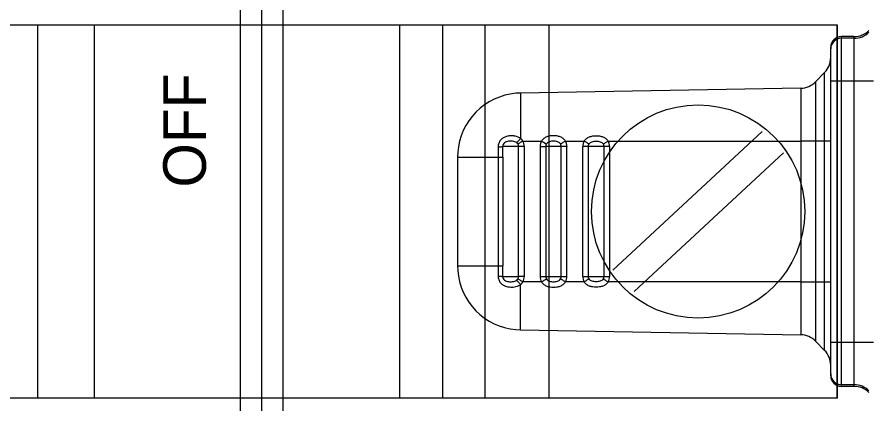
# Model space of a CAD drawing. Extents: x 0 to 4205, y 0 to 2970.
# Drawn here: x 958.55 to 998.5, y 1083.32 to 1101.46 of the extents above; entities that cross this region are included whole.
import ezdxf

# ---------------------------------------------------------------- set-up
doc = ezdxf.new("R2010")
doc.units = 0
doc.layers.add('Level 1', color=7, linetype='Continuous')

# ---------------------------------------------------------------- blocks, each defined once
blk = doc.blocks.new('NCX-2418-3U')
for p, q in [((-178, 132.85), (-178, -99.15)), ((-177, 132.85), (-177, -99.15)), ((-176, 132.85), (-176, -99.15)), ((-149.8, 17.451), (-149.8, 33.849)), ((-149.214, 33.849), (-149.8, 33.849)), ((-149.214, 33.849), (-149.8, 33.849)), ((-149.214, 33.77), (-149.8, 33.77)), ((-149.214, 33.849), (-149.214, 17.451)), ((-150.3, 17.951), (-150.3, 33.349)), ((-150.587, 32.164), (-151.013, 31.73)), ((-150.587, 19.136), (-150.587, 32.164)), ((-151.013, 31.73), (-151.013, 19.57)), ((-150.3, 31.771), (-148.3, 31.771)), ((-151.709, 31.431), (-164.852, 31.201)), ((-164.852, 31.201), (-164.852, 29.074)), ((-151.709, 31.431), (-151.709, 19.869)), ((-164.735, 28.95), (-163.865, 28.95)), ((-162.735, 28.95), (-161.865, 28.95)), ((-160.735, 28.95), (-151.709, 28.95)), ((-150.3, 28.95), (-151.709, 28.95)), ((-164.668, 28.7), (-165.674, 28.7)), ((-164.942, 22.6), (-164.942, 28.7)), ((-164.668, 22.6), (-164.668, 28.7)), ((-163.932, 28.7), (-163.932, 22.6)), ((-163.932, 28.7), (-163.664, 28.7)), ((-163.664, 28.7), (-163.664, 22.6)), ((-162.942, 28.7), (-163.664, 28.7)), ((-162.942, 22.6), (-162.942, 28.7)), ((-162.668, 28.7), (-162.942, 28.7)), ((-162.668, 22.6), (-162.668, 28.7)), ((-161.932, 22.6), (-161.932, 28.7)), ((-160.668, 28.7), (-161.932, 28.7)), ((-161.664, 22.6), (-161.664, 28.7)), ((-160.942, 28.7), (-160.942, 22.6)), ((-160.668, 28.7), (-160.668, 22.6)), ((-167.8, 28.202), (-167.8, 23.098)), ((-167.8, 28.202), (-165.67, 28.202)), ((-165.902, 28.202), (-165.902, 23.098)), ((-165.67, 28.202), (-165.67, 23.098)), ((-167.8, 23.098), (-165.902, 23.098)), ((-165.902, 23.098), (-165.67, 23.098)), ((-165.674, 22.6), (-164.942, 22.6)), ((-164.668, 22.6), (-164.942, 22.6)), ((-163.932, 22.6), (-162.668, 22.6)), ((-161.932, 22.6), (-160.668, 22.6)), ((-164.852, 20.099), (-164.852, 22.225)), ((-163.865, 22.35), (-164.735, 22.35)), ((-161.865, 22.35), (-162.735, 22.35)), ((-151.709, 22.35), (-160.735, 22.35)), ((-151.709, 22.35), (-150.3, 22.35)), ((-164.852, 20.099), (-151.709, 19.869)), ((-151.013, 19.57), (-150.587, 19.136)), ((-150.3, 19.529), (-148.3, 19.529)), ((-149.8, 17.53), (-149.214, 17.53)), ((-149.214, 17.451), (-149.8, 17.451)), ((-149.214, 17.451), (-149.8, 17.451))]:
    blk.add_line(p, q)
for points in [[(-164.852, 31.201), (-165.07, 31.19), (-165.331, 31.155), (-165.588, 31.096), (-165.84, 31.016), (-166.083, 30.914), (-166.316, 30.791), (-166.537, 30.648), (-166.746, 30.486), (-166.939, 30.306), (-167.115, 30.11), (-167.274, 29.899), (-167.413, 29.676), (-167.532, 29.44), (-167.631, 29.196), (-167.707, 28.943), (-167.761, 28.685), (-167.792, 28.423), (-167.8, 28.202)], [(-167.8, 23.098), (-167.792, 22.88), (-167.761, 22.619), (-167.708, 22.36), (-167.632, 22.108), (-167.534, 21.863), (-167.415, 21.628), (-167.276, 21.404), (-167.117, 21.193), (-166.941, 20.997), (-166.748, 20.817), (-166.541, 20.655), (-166.319, 20.511), (-166.086, 20.388), (-165.843, 20.285), (-165.592, 20.205), (-165.335, 20.146), (-165.073, 20.111), (-164.852, 20.099)]]:
    blk.add_lwpolyline(points)
for centre, radius, start, end in [((-149.214, 34.849), 1, 270, 315), ((-149.214, 34.849), 1, 269.9984, 314.9877), ((-149.214, 34.77), 1, 269.9984, 314.9877), ((-149.8, 33.349), 0.5, 90, 180), ((-149.8, 33.349), 0.5, 89.9895, 179.9895), ((-149.8, 33.27), 0.5, 89.9895, 179.9895), ((-151.3, 32.865), 1, 315.5, 359.9974), ((-151.726, 32.431), 1, 271, 315.4998), ((-165.167, 28.7), 0.499, 0.0299, 30.0713), ((-163.433, 28.7), 0.5, 149.9278, 179.963), ((-163.167, 28.7), 0.5, 0.0336, 30.0749), ((-161.433, 28.7), 0.499, 149.9288, 179.9703), ((-161.167, 28.7), 0.499, 0.0299, 30.0709), ((-194.009, 28.214), 28.339, 359.9754, 0.9825), ((-194.015, 23.086), 28.344, 359.0176, 0.0247), ((-165.167, 22.6), 0.499, 329.9312, 359.969), ((-163.433, 22.6), 0.5, 180.0364, 210.0773), ((-163.447, 22.6), 0.217, 180.0423, 211.5562), ((-163.167, 22.6), 0.499, 329.9303, 359.9687), ((-161.433, 22.6), 0.499, 180.0293, 210.0718), ((-161.167, 22.6), 0.499, 329.9282, 359.9708), ((-151.726, 18.869), 1, 44.5002, 89), ((-151.3, 18.435), 1, 0.0453, 44.5), ((-149.8, 18.03), 0.5, 180.0105, 270.0105), ((-149.8, 17.951), 0.5, 180, 270), ((-149.8, 17.951), 0.5, 180.0105, 270.0105), ((-149.214, 16.53), 1, 45.0123, 90.0016), ((-149.214, 16.451), 1, 45.0123, 90.0016), ((-149.214, 16.451), 1, 45, 90)]:
    blk.add_arc(centre, radius, start, end)
for points, degree in [([(-164.852, 29.074), (-164.897, 29.109), (-164.998, 29.163), (-165.166, 29.197), (-165.336, 29.197), (-165.504, 29.174), (-165.663, 29.109), (-165.794, 28.997), (-165.88, 28.848), (-165.901, 28.734), (-165.901, 28.678)], 3), ([(-162.735, 28.95), (-162.764, 28.995), (-162.839, 29.075), (-162.981, 29.154), (-163.139, 29.194), (-163.3, 29.204), (-163.461, 29.194), (-163.618, 29.154), (-163.761, 29.075), (-163.836, 28.995), (-163.865, 28.95)], 3), ([(-161.865, 28.95), (-161.836, 28.995), (-161.761, 29.075), (-161.619, 29.155), (-161.461, 29.194), (-161.3, 29.204), (-161.138, 29.194), (-160.981, 29.155), (-160.839, 29.075), (-160.764, 28.995), (-160.735, 28.95)], 3), ([(-165.031, 28.878), (-165.057, 28.898), (-165.119, 28.928), (-165.217, 28.942), (-165.316, 28.945), (-165.414, 28.942), (-165.511, 28.927), (-165.6, 28.881), (-165.662, 28.801), (-165.676, 28.733), (-165.674, 28.7)], 3), ([(-164.852, 29.074), (-164.887, 29.034), (-164.935, 28.978), (-164.996, 28.913), (-165.021, 28.888), (-165.031, 28.878)], 3), ([(-164.974, 28.814), (-164.989, 28.838), (-165.009, 28.86), (-165.031, 28.878)], 2), ([(-164.735, 28.95), (-164.782, 28.923), (-164.861, 28.877), (-164.941, 28.832), (-164.974, 28.814)], 3), ([(-164.942, 28.7), (-164.942, 28.72), (-164.947, 28.76), (-164.964, 28.797), (-164.974, 28.814)], 3), ([(-164.735, 28.95), (-164.766, 28.998), (-164.807, 29.04), (-164.852, 29.074)], 2), ([(-163.865, 28.95), (-163.819, 28.923), (-163.741, 28.878), (-163.663, 28.832), (-163.632, 28.814)], 3), ([(-163.632, 28.814), (-163.643, 28.797), (-163.659, 28.76), (-163.664, 28.72), (-163.664, 28.7)], 3), ([(-162.974, 28.814), (-162.99, 28.84), (-163.033, 28.887), (-163.119, 28.927), (-163.211, 28.941), (-163.304, 28.943), (-163.396, 28.941), (-163.488, 28.927), (-163.573, 28.887), (-163.616, 28.84), (-163.632, 28.814)], 3), ([(-162.735, 28.95), (-162.782, 28.923), (-162.861, 28.877), (-162.941, 28.832), (-162.974, 28.814)], 3), ([(-162.942, 28.7), (-162.942, 28.72), (-162.947, 28.76), (-162.964, 28.797), (-162.974, 28.814)], 3), ([(-161.632, 28.814), (-161.663, 28.832), (-161.741, 28.878), (-161.819, 28.923), (-161.865, 28.95)], 3), ([(-161.664, 28.7), (-161.664, 28.739), (-161.653, 28.78), (-161.632, 28.814)], 2), ([(-161.632, 28.814), (-161.616, 28.84), (-161.573, 28.887), (-161.488, 28.927), (-161.396, 28.941), (-161.304, 28.943), (-161.211, 28.941), (-161.119, 28.927), (-161.033, 28.887), (-160.99, 28.84), (-160.974, 28.814)], 3), ([(-160.974, 28.814), (-160.941, 28.832), (-160.861, 28.877), (-160.782, 28.923), (-160.735, 28.95)], 3), ([(-160.974, 28.814), (-160.964, 28.797), (-160.947, 28.76), (-160.942, 28.72), (-160.942, 28.7)], 3), ([(-165.901, 28.678), (-165.901, 28.519), (-165.902, 28.361), (-165.902, 28.202)], 2), ([(-165.901, 28.678), (-165.854, 28.68), (-165.791, 28.684), (-165.716, 28.692), (-165.686, 28.697), (-165.674, 28.7)], 3), ([(-165.902, 23.098), (-165.902, 22.94), (-165.901, 22.781), (-165.901, 22.622)], 2), ([(-165.901, 22.622), (-165.854, 22.62), (-165.791, 22.616), (-165.716, 22.608), (-165.686, 22.603), (-165.674, 22.6)], 3), ([(-165.901, 22.622), (-165.901, 22.566), (-165.88, 22.452), (-165.794, 22.303), (-165.663, 22.191), (-165.504, 22.126), (-165.364, 22.106), (-165.251, 22.103), (-165.138, 22.109), (-164.998, 22.137), (-164.897, 22.191), (-164.852, 22.225)], 3), ([(-165.674, 22.6), (-165.676, 22.567), (-165.662, 22.499), (-165.6, 22.419), (-165.511, 22.373), (-165.414, 22.358), (-165.316, 22.355), (-165.217, 22.358), (-165.119, 22.372), (-165.058, 22.402), (-165.031, 22.422)], 3), ([(-165.031, 22.422), (-165.009, 22.44), (-164.989, 22.462), (-164.974, 22.486)], 2), ([(-164.852, 22.225), (-164.887, 22.266), (-164.935, 22.322), (-164.996, 22.387), (-165.021, 22.412), (-165.031, 22.422)], 3), ([(-164.974, 22.486), (-164.964, 22.503), (-164.947, 22.54), (-164.942, 22.58), (-164.942, 22.6)], 3), ([(-164.735, 22.35), (-164.782, 22.377), (-164.861, 22.423), (-164.941, 22.468), (-164.974, 22.486)], 3), ([(-163.865, 22.35), (-163.819, 22.377), (-163.741, 22.422), (-163.663, 22.468), (-163.632, 22.486)], 3), ([(-163.632, 22.486), (-163.616, 22.46), (-163.573, 22.413), (-163.488, 22.373), (-163.396, 22.359), (-163.304, 22.357), (-163.211, 22.359), (-163.119, 22.373), (-163.033, 22.413), (-162.99, 22.46), (-162.974, 22.486)], 3), ([(-162.974, 22.486), (-162.964, 22.503), (-162.947, 22.54), (-162.942, 22.58), (-162.942, 22.6)], 3), ([(-162.735, 22.35), (-162.782, 22.377), (-162.861, 22.423), (-162.941, 22.468), (-162.974, 22.486)], 3), ([(-161.632, 22.486), (-161.663, 22.468), (-161.741, 22.422), (-161.819, 22.377), (-161.865, 22.35)], 3), ([(-161.632, 22.486), (-161.643, 22.503), (-161.659, 22.54), (-161.664, 22.58), (-161.664, 22.6)], 3), ([(-160.974, 22.486), (-160.99, 22.46), (-161.033, 22.413), (-161.119, 22.373), (-161.211, 22.359), (-161.304, 22.357), (-161.396, 22.359), (-161.488, 22.373), (-161.573, 22.413), (-161.616, 22.46), (-161.632, 22.486)], 3), ([(-160.942, 22.6), (-160.942, 22.58), (-160.947, 22.54), (-160.964, 22.503), (-160.974, 22.486)], 3), ([(-160.974, 22.486), (-160.941, 22.468), (-160.861, 22.423), (-160.782, 22.377), (-160.735, 22.35)], 3), ([(-164.852, 22.225), (-164.807, 22.26), (-164.766, 22.302), (-164.735, 22.35)], 2), ([(-163.865, 22.35), (-163.836, 22.305), (-163.761, 22.225), (-163.618, 22.146), (-163.461, 22.106), (-163.3, 22.096), (-163.138, 22.106), (-162.981, 22.146), (-162.839, 22.225), (-162.764, 22.305), (-162.735, 22.35)], 3), ([(-160.735, 22.35), (-160.764, 22.305), (-160.839, 22.225), (-160.981, 22.145), (-161.138, 22.106), (-161.3, 22.096), (-161.461, 22.106), (-161.619, 22.145), (-161.761, 22.225), (-161.836, 22.305), (-161.865, 22.35)], 3)]:
    blk.add_open_spline(points, degree=degree)

msp = doc.modelspace()

# ---------------------------------------------------------------- linework, layer by layer
at = {"layer": 'Level 1'}
for p, q in [((914.008, 1101.093), (997.008, 1101.093)), ((959.508, 1101.093), (959.508, 1083.593)), ((962.161, 1101.093), (962.161, 1083.593)), ((976.508, 1083.593), (976.508, 1101.093)), ((978.508, 1101.093), (978.508, 1083.593)), ((980.508, 1083.593), (980.508, 1101.093)), ((983.49, 1101.093), (983.49, 1083.593)), ((997.008, 1083.593), (997.008, 1101.093)), ((993.49, 1096.093), (986.49, 1089.593)), ((987.49, 1088.593), (994.49, 1095.093)), ((997.008, 1083.593), (914.008, 1083.593))]:
    msp.add_line(p, q, dxfattribs=at)
msp.add_lwpolyline([(914.008, 1083.593), (914.008, 1101.093), (997.008, 1101.093), (997.008, 1083.593)], close=True, dxfattribs=at)
msp.add_lwpolyline([(914.008, 1083.593), (914.008, 1101.093), (997.008, 1101.093), (997.008, 1083.593)], close=True, dxfattribs=at)
msp.add_circle((990.49, 1092.343), 5, dxfattribs=at)

# ---------------------------------------------------------------- block references
msp.add_blockref('NCX-2418-3U', (1147.008, 1066.693))

# ---------------------------------------------------------------- texts
msp.add_text('OFF', height=2, rotation=90, dxfattribs=at).set_placement((967.406, 1093.466))

doc.saveas('drawing.dxf')
